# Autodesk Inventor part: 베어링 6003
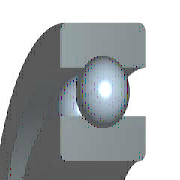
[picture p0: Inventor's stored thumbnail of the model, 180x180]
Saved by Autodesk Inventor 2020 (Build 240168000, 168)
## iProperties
Created: 2012-02
Part Number: 베어링 6003
Material: 강철, 연강
Description: 깊은 그루브 볼 베어링
Document SubType Name: Modeling
Standard: KS B 2023
Designer: mduedu
Standards Organization: KS
Language: ko-KR
Size Designation: 6003 - 17 x 35 x 10
Categories: <MemberInstance><Categories><Category DisplayName="샤프트 부품" InternalName="7f7aeb1f-a693-4053-b835-cee3144e0d98" Mnemonic="SHFT"><Category DisplayName="베어링" Inter
Density: 1 g/cm^3
Appearance: 노란색
IsCustomPart: 1
Author: mduedu
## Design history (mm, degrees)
sketch "스케치" dims "d0" = 4.68 (= -0.26 x WD + 0.26 x BD)
  geometry: L1 (2.66, 13)-(7.34, 13); L2 (5, 13)-(5, 10.66); L3 (5, 13)-(5, 15.34); L4 (3.261, 11.434)-(0, 11.434); L5 (0, 8.5)-(10, 8.5); L6 (3.261, 14.566)-(0, 14.566); L7 (0, 17.5)-(10, 17.5); L8 (10, 8.5)-(10, 11.434); L9 (6.739, 11.434)-(10, 11.434); L10 (6.739, 14.566)-(10, 14.566); L11 (10, 17.5)-(10, 14.566); L12 (-1.4, 0)-(8.4, 0) reference; L13 (0, -0.3)-(0, 5.3) reference
  constraints: 22 end point, 4 point on line, 2 collinear, 2 perpendicular, 2 symmetric about line, 1 midpoint, 1 parallel, 14 other
  dimensions: "d9" = 17 diameter of L5 L12 (= WD); "d11" = 35 diameter of L7 L12 (= BD); "d12" = 10 distance between parallel lines of L8 L13 (= KB); "d13" = 22.868 diameter of L9 L12 (= 0.326 x BD + 0.674 x WD)
revolve "본체" stored, may be unused: angle "d6" = 90 deg
revolve "볼" stored, may be unused: angle "d7" = 90 deg
pattern_circular "IDS_ARRAYBALL[SIMPL:T]" dims angle "d3" = 360 deg
body "Solid1"
fillet "모깎기1" dims "d1" = 0.3 (= KRS)
other parameters: "WD" = 17 [user parameter; used in 5 equation terms], "BD" = 35 [user parameter; used in 5 equation terms], "KB" = 10 [user parameter; used in 1 equation term], "KRS" = 0.3 [user parameter; used in 1 equation term], "d4" = 0, "d5" = 0, "d8" = 0, "d14" = 0, "d15" = 0, "BBA" = 0 [user parameter], "BC0" = 3250000 [user parameter], "BC" = 6050000 [user parameter], "BR" = 17.5 (= 0.5 x BD) [user parameter], "WR" = 8.5 (= 0.5 x WD) [user parameter]
